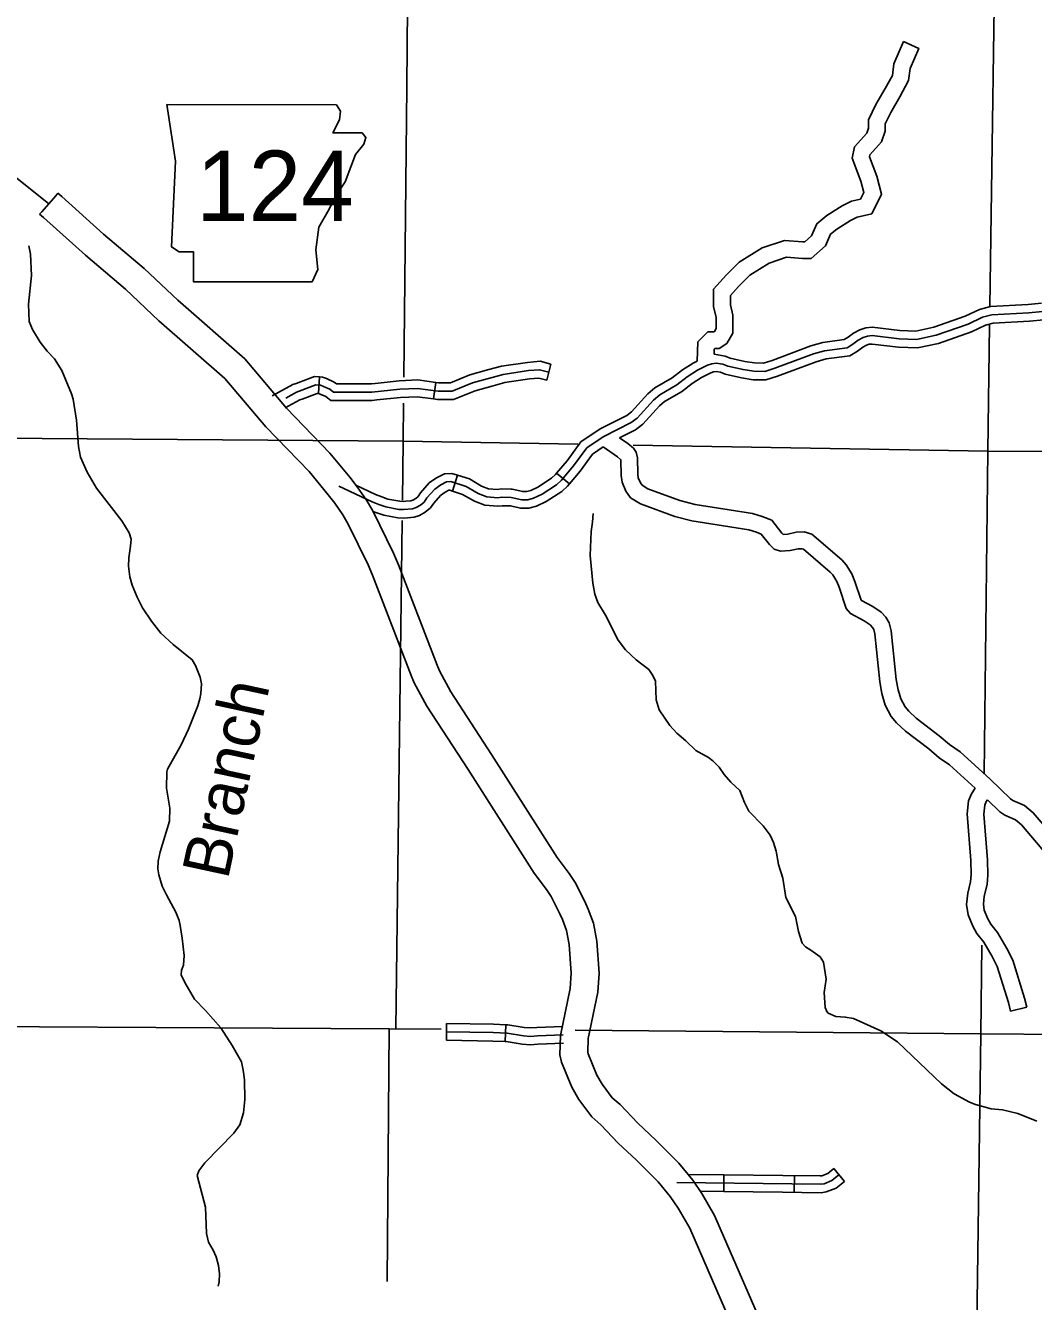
# Model space of a CAD drawing. Extents: x 1373862 to 1376999, y 1168398 to 1170455.
# Drawn here: x 1375806.5 to 1375987.3, y 1168745.9 to 1168974.9 of the extents above; entities that cross this region are included whole.
import ezdxf

# ---------------------------------------------------------------- set-up
doc = ezdxf.new("R2010")
doc.units = 0
for name, color, linetype in [('Level 10', 7, 'Continuous'), ('Level 21', 7, 'Continuous'), ('Level 32', 7, 'Continuous'), ('Level 35', 7, 'Continuous'), ('Level 4', 7, 'Continuous'), ('Level 45', 7, 'Continuous'), ('Level 46', 7, 'Continuous'), ('Level 5', 7, 'Continuous')]:
    doc.layers.add(name, color=color, linetype=linetype)

msp = doc.modelspace()

# ---------------------------------------------------------------- linework, layer by layer
at = {"layer": 'Level 10'}
for points in [[(1375810.66, 1168942.85), (1375802.81, 1168949.14), (1375798.84, 1168952.2), (1375796.61, 1168953.74), (1375794.39, 1168954.87), (1375775.91, 1168959.64), (1375772.5, 1168960.73), (1375771.74, 1168961.21), (1375770.37, 1168962.36), (1375769.5, 1168963.6), (1375769.9, 1169002.68)], [(1375907.42, 1168793.06), (1375909.18, 1168801.4), (1375909.38, 1168804.82), (1375908.98, 1168810.57), (1375908.37, 1168813.81), (1375907.44, 1168816.28), (1375906.83, 1168817.69), (1375905.11, 1168821.05), (1375904.04, 1168822.71), (1375901.86, 1168825.59), (1375890.1, 1168844.04), (1375882.79, 1168855.29), (1375880.73, 1168859.09), (1375880.3, 1168860.1), (1375873.38, 1168878.1), (1375872.5, 1168880.18), (1375868.76, 1168887.77), (1375867.63, 1168889.72), (1375865.99, 1168892.1), (1375864.65, 1168893.8), (1375861.07, 1168898.14), (1375853.31, 1168906.19), (1375845.81, 1168915.03), (1375833.76, 1168925.58), (1375827.75, 1168931.3), (1375820.47, 1168937.44), (1375812.95, 1168944.22), (1375812.27, 1168944.77)], [(1375808.96, 1168941.01), (1375809.71, 1168940.41), (1375817.19, 1168933.67), (1375824.41, 1168927.58), (1375830.39, 1168921.89), (1375842.24, 1168911.51), (1375849.6, 1168902.83), (1375857.34, 1168894.81), (1375860.76, 1168890.66), (1375861.96, 1168889.13), (1375863.4, 1168887.05), (1375864.34, 1168885.41), (1375867.95, 1168878.1), (1375868.74, 1168876.23), (1375875.66, 1168858.23), (1375876.22, 1168856.92), (1375878.49, 1168852.73), (1375885.89, 1168841.34), (1375897.75, 1168822.74), (1375899.94, 1168819.84), (1375900.77, 1168818.55), (1375902.3, 1168815.56), (1375902.8, 1168814.41), (1375903.54, 1168812.45), (1375904.01, 1168809.93), (1375904.37, 1168804.79), (1375904.21, 1168802.07), (1375902.43, 1168793.65)], [(1375902.43, 1168793.65), (1375902.35, 1168790.14), (1375902.63, 1168788.81), (1375904.5, 1168784.33), (1375905.74, 1168782.14), (1375908.07, 1168779.04), (1375909.69, 1168777.61), (1375912.79, 1168774.31), (1375916.12, 1168771.22), (1375919.99, 1168767.37), (1375922.16, 1168764.7), (1375923.56, 1168762.62), (1375925.64, 1168759.06), (1375935.97, 1168735.29)], [(1375940.58, 1168737.24), (1375930.11, 1168761.33), (1375927.8, 1168765.29), (1375926.18, 1168767.68), (1375923.71, 1168770.73), (1375919.59, 1168774.82), (1375916.32, 1168777.86), (1375913.17, 1168781.21), (1375911.76, 1168782.45), (1375909.93, 1168784.88), (1375909, 1168786.53), (1375907.42, 1168790.31), (1375907.36, 1168790.61), (1375907.42, 1168793.06)]]:
    msp.add_lwpolyline(points, dxfattribs=at)
msp.add_arc((1375767.96, 1168980.41), 56.86, 316.1417, 321.187, dxfattribs=at)
at = {"layer": 'Level 21'}
msp.add_lwpolyline([(1375831.83, 1168960.69), (1375833.35, 1168950.54), (1375832.68, 1168935.14), (1375834.03, 1168934.29), (1375836.57, 1168934.29), (1375836.57, 1168928.88), (1375857.88, 1168928.88), (1375858.9, 1168931.08), (1375858.56, 1168934.63), (1375859.07, 1168938.69), (1375860.93, 1168941.91), (1375862.11, 1168944.28), (1375863.81, 1168946.81), (1375864.82, 1168949.52), (1375865.67, 1168951.72), (1375867.19, 1168953.58), (1375867.53, 1168954.76), (1375866.85, 1168955.61), (1375861.61, 1168955.61), (1375862.79, 1168957.98), (1375862.96, 1168959.5), (1375862.26, 1168960.67)], close=True, dxfattribs=at)
at = {"layer": 'Level 32'}
for p, q in [((1375881.98, 1168792.77), (1375882.03, 1168795.77)), ((1375892.5, 1168792.54), (1375892.63, 1168795.54)), ((1375951.5, 1168769.73), (1375953.4, 1168767.41)), ((1375931.8, 1168768.62), (1375931.76, 1168765.62)), ((1375944.41, 1168765.46), (1375944.45, 1168768.46))]:
    msp.add_line(p, q, dxfattribs=at)
for points in [[(1375882.03, 1168795.77), (1375890.42, 1168795.63), (1375892.63, 1168795.54)], [(1375892.63, 1168795.54), (1375893.03, 1168795.52), (1375895.96, 1168795.05), (1375897.09, 1168794.97), (1375898.23, 1168795.05), (1375902.9, 1168795.23)], [(1375881.98, 1168792.77), (1375890.33, 1168792.63), (1375892.5, 1168792.54)], [(1375882.01, 1168794.27), (1375890.37, 1168794.13), (1375892.88, 1168794.03), (1375895.79, 1168793.56), (1375897.1, 1168793.46), (1375898.32, 1168793.56), (1375902.95, 1168793.74)], [(1375892.5, 1168792.54), (1375892.72, 1168792.53), (1375895.61, 1168792.06), (1375897.1, 1168791.96), (1375898.41, 1168792.06), (1375903.01, 1168792.24)], [(1375951.5, 1168769.73), (1375950.43, 1168768.86), (1375949.37, 1168768.46), (1375949.04, 1168768.41), (1375942.36, 1168768.49)], [(1375931.8, 1168768.62), (1375925.35, 1168768.7)], [(1375942.36, 1168768.49), (1375931.8, 1168768.62)], [(1375953.4, 1168767.41), (1375951.95, 1168766.23), (1375950.15, 1168765.55), (1375949.26, 1168765.4), (1375942.32, 1168765.49)], [(1375931.76, 1168765.62), (1375927.57, 1168765.68)], [(1375942.32, 1168765.49), (1375931.76, 1168765.62)]]:
    msp.add_lwpolyline(points, dxfattribs=at)
at = {"layer": 'Level 35'}
for points in [[(1375843.53, 1168791.82), (1375841.51, 1168794.98), (1375838.78, 1168798.09), (1375836.77, 1168800.12), (1375835.02, 1168803.13), (1375834.37, 1168804.53), (1375834.47, 1168805.33), (1375834.78, 1168806.23), (1375834.93, 1168807.96), (1375834.59, 1168811.06), (1375834.21, 1168813.36), (1375834, 1168814.26), (1375833.41, 1168815.74), (1375831.73, 1168818.85), (1375830.97, 1168820.45), (1375830.38, 1168822.43), (1375830.19, 1168823.51), (1375830.24, 1168824.89), (1375830.59, 1168826.56), (1375832.29, 1168832.08), (1375832.37, 1168834.43), (1375831.73, 1168837.99), (1375831.79, 1168840.96), (1375831.94, 1168841.44), (1375834.4, 1168845.77), (1375835.7, 1168848.62), (1375837.37, 1168852.76), (1375837.76, 1168854.07), (1375837.91, 1168855.01), (1375838.04, 1168856.75), (1375837.81, 1168857.95), (1375836.98, 1168860.01), (1375836.39, 1168861.05), (1375832.96, 1168863.81), (1375830.75, 1168865.8), (1375829.07, 1168867.99), (1375827.45, 1168870.38), (1375826.49, 1168872.3), (1375825.62, 1168874.47), (1375825.17, 1168875.93), (1375824.95, 1168877.85), (1375824.98, 1168879.36), (1375825.31, 1168881.44), (1375825.4, 1168882.67), (1375825.05, 1168883.83), (1375823.71, 1168885.98), (1375819.22, 1168891.86), (1375817.54, 1168894.71), (1375816.3, 1168897.39), (1375815.98, 1168899.31), (1375815.63, 1168904.07), (1375815.02, 1168907.84), (1375814.71, 1168908.8), (1375812.96, 1168912.99), (1375811.65, 1168915.04), (1375810.31, 1168916.42), (1375809.1, 1168918.05), (1375807.68, 1168920.32), (1375807.11, 1168921.76), (1375806.99, 1168924.85), (1375807.51, 1168930), (1375807.34, 1168933.83), (1375807.07, 1168935.33)], [(1375908.32, 1168887.31), (1375908.23, 1168885.77), (1375907.97, 1168884.05), (1375907.8, 1168879.74), (1375908.28, 1168874.8), (1375908.62, 1168872.8), (1375909.14, 1168871.31), (1375910.51, 1168869.06), (1375912.83, 1168864.56), (1375914.11, 1168862.84), (1375916.06, 1168861.02), (1375918.29, 1168859.32), (1375919.02, 1168858.23), (1375919.49, 1168857.23), (1375919.63, 1168853.89), (1375920.17, 1168852.04), (1375922.09, 1168849.28), (1375923.31, 1168847.85), (1375924.97, 1168846.51), (1375926.76, 1168844.77), (1375929, 1168843.53), (1375929.81, 1168842.92), (1375930.94, 1168841.79), (1375931.83, 1168840.44), (1375933.01, 1168839.07), (1375934.65, 1168837.61), (1375935.47, 1168835.46), (1375936.28, 1168833.87), (1375938.85, 1168831.25), (1375940.06, 1168829.58), (1375940.67, 1168828.27), (1375941.17, 1168826.68), (1375941.6, 1168824.32), (1375942.35, 1168821.85), (1375942.89, 1168818.37), (1375944.64, 1168815), (1375945.17, 1168812.31), (1375945.84, 1168810.22), (1375946.4, 1168809.54), (1375947.41, 1168808.95), (1375949.04, 1168807.72), (1375949.63, 1168806.76), (1375950.16, 1168803.76), (1375949.75, 1168801.31), (1375949.94, 1168798.67), (1375950.25, 1168797.93), (1375950.51, 1168797.6), (1375951.88, 1168797.06), (1375953.56, 1168796.94), (1375955.04, 1168796.65), (1375959.94, 1168794.44), (1375962.93, 1168792.46), (1375970.85, 1168784.94), (1375973.13, 1168783.13), (1375975.88, 1168781.66), (1375976.91, 1168781.21), (1375979.73, 1168780.44), (1375981.76, 1168780.29), (1375984.55, 1168779.62), (1375987.94, 1168778.24)], [(1375843.53, 1168791.82), (1375845.22, 1168788.91), (1375845.52, 1168787.38), (1375845.73, 1168785.64), (1375845.83, 1168782.13), (1375845.55, 1168779.74), (1375844.89, 1168777.59), (1375843.85, 1168776.1), (1375838.66, 1168770.76), (1375837.55, 1168769.36), (1375837.28, 1168768.51), (1375838.75, 1168762.8), (1375838.91, 1168758.07), (1375839.28, 1168756.54), (1375840.1, 1168755.11), (1375840.66, 1168753.92), (1375841.08, 1168752.33), (1375841.25, 1168750.83), (1375841.19, 1168749.43), (1375841.03, 1168748.65)]]:
    msp.add_lwpolyline(points, dxfattribs=at)
at = {"layer": 'Level 4'}
for points in [[(1375881.05, 1168794.75), (1375871.72, 1168794.83), (1375767.06, 1168795.43)], [(1375977.91, 1168793.92), (1375905.11, 1168794.55)], [(1375977.91, 1168793.92), (1376008.61, 1168793.71)]]:
    msp.add_lwpolyline(points, dxfattribs=at)
at = {"layer": 'Level 45'}
for p, q in [((1375900.75, 1168914.12), (1375899.99, 1168911.22)), ((1375859.22, 1168911.82), (1375859.01, 1168908.83)), ((1375880.07, 1168910.83), (1375879.66, 1168907.86)), ((1375884, 1168894.18), (1375883.09, 1168891.32)), ((1375901.77, 1168894.54), (1375904.07, 1168892.61))]:
    msp.add_line(p, q, dxfattribs=at)
for points in [[(1375988.98, 1168923.56), (1375986.52, 1168923.34), (1375979.89, 1168922.97), (1375978.19, 1168922.51), (1375975.62, 1168921.31), (1375969.88, 1168919.28), (1375966.37, 1168918.53), (1375963.22, 1168918.63), (1375958.39, 1168919.23), (1375957.55, 1168919.15), (1375956.75, 1168918.9), (1375955.89, 1168918.41), (1375954.93, 1168917.68), (1375953.9, 1168917.06), (1375949.84, 1168916.52), (1375947.88, 1168915.95), (1375940.93, 1168913.37), (1375939.11, 1168912.81), (1375937.16, 1168912.82), (1375935.24, 1168913.13), (1375932.47, 1168913.75), (1375931.61, 1168914.1), (1375930.4, 1168914.29), (1375929.6, 1168914.18), (1375928.84, 1168913.94), (1375927.03, 1168913), (1375925.21, 1168911.85), (1375923.34, 1168910.37), (1375920.27, 1168908.62), (1375919.17, 1168907.67), (1375916.19, 1168904.42), (1375915.14, 1168903.61), (1375910.11, 1168901.07), (1375907.16, 1168899.08)], [(1375900.75, 1168914.12), (1375898.83, 1168914.63), (1375896.52, 1168914.43), (1375891.87, 1168913.74), (1375889.61, 1168913.12)], [(1375859.22, 1168911.82), (1375858.32, 1168911.89), (1375855.05, 1168910.65), (1375854.45, 1168910.44), (1375850.72, 1168908.42)], [(1375900.37, 1168912.67), (1375898.7, 1168913.11), (1375896.7, 1168912.94), (1375892.18, 1168912.27), (1375886.66, 1168910.77), (1375882.99, 1168909.26), (1375880.48, 1168909.26), (1375876.8, 1168909.76), (1375873.62, 1168909.6), (1375868.61, 1168909.09), (1375864.43, 1168909.09), (1375861.75, 1168909.09), (1375861.08, 1168909.6), (1375859.9, 1168910.12), (1375859.39, 1168910.31), (1375858.55, 1168910.37), (1375855.56, 1168909.24), (1375855.06, 1168909.06), (1375853.16, 1168908.03)], [(1375869.21, 1168910.66), (1375868.53, 1168910.59), (1375864.43, 1168910.59), (1375862.25, 1168910.59), (1375861.85, 1168910.9), (1375860.47, 1168911.5), (1375859.72, 1168911.79), (1375859.22, 1168911.82)], [(1375889.61, 1168913.12), (1375886.18, 1168912.19), (1375882.69, 1168910.76), (1375880.58, 1168910.76), (1375880.07, 1168910.83)], [(1375899.99, 1168911.22), (1375898.57, 1168911.59), (1375896.87, 1168911.45), (1375892.49, 1168910.8), (1375890.4, 1168910.23)], [(1375880.07, 1168910.83), (1375876.86, 1168911.27), (1375873.51, 1168911.09), (1375869.21, 1168910.66)], [(1375890.4, 1168910.23), (1375887.15, 1168909.34), (1375883.28, 1168907.76), (1375880.38, 1168907.76), (1375879.66, 1168907.86)], [(1375859.01, 1168908.83), (1375858.77, 1168908.85), (1375856.08, 1168907.83), (1375855.67, 1168907.69), (1375853.02, 1168906.25)], [(1375869.51, 1168907.68), (1375868.68, 1168907.59), (1375864.43, 1168907.59), (1375861.25, 1168907.59), (1375860.32, 1168908.29), (1375859.33, 1168908.73), (1375859.06, 1168908.83), (1375859.01, 1168908.83)], [(1375879.66, 1168907.86), (1375876.74, 1168908.26), (1375873.74, 1168908.1), (1375869.51, 1168907.68)], [(1375909.55, 1168902.47), (1375906.12, 1168900.16), (1375903.64, 1168896.77), (1375901.77, 1168894.54)], [(1375907.16, 1168899.08), (1375904.8, 1168895.86), (1375902.63, 1168893.28), (1375901.74, 1168892.47), (1375899.15, 1168890.77), (1375897.63, 1168890.03), (1375896.59, 1168889.77), (1375895.51, 1168889.78), (1375893.6, 1168890.2), (1375891.9, 1168890.23), (1375891.2, 1168890.14), (1375889.22, 1168890.29), (1375887.67, 1168890.88), (1375885.52, 1168892.14), (1375882.77, 1168893.03), (1375882.03, 1168892.98), (1375880.97, 1168892.45), (1375879.89, 1168891.68), (1375878.5, 1168890.09), (1375877.99, 1168889.36), (1375877.31, 1168888.8), (1375876.55, 1168888.37), (1375875.89, 1168888.14), (1375874.29, 1168887.99), (1375873.45, 1168888.02), (1375871.12, 1168888.47), (1375869.88, 1168888.9), (1375868.69, 1168889.37), (1375862.7, 1168892.23)], [(1375910.14, 1168899.25), (1375908.23, 1168897.97), (1375906, 1168894.92), (1375904.07, 1168892.61)], [(1375884, 1168894.18), (1375882.95, 1168894.51), (1375881.64, 1168894.43), (1375880.21, 1168893.72), (1375878.9, 1168892.78), (1375877.34, 1168891), (1375876.9, 1168890.37), (1375876.47, 1168890.01), (1375875.95, 1168889.72), (1375875.58, 1168889.59), (1375874.73, 1168889.51)], [(1375893.58, 1168891.68), (1375891.82, 1168891.7), (1375891.16, 1168891.62), (1375889.54, 1168891.74), (1375888.31, 1168892.21), (1375886.12, 1168893.5), (1375884, 1168894.18)], [(1375901.77, 1168894.54), (1375901.57, 1168894.3), (1375900.84, 1168893.64), (1375898.42, 1168892.05), (1375897.12, 1168891.42), (1375896.41, 1168891.24), (1375895.68, 1168891.25), (1375893.78, 1168891.67), (1375893.58, 1168891.68)], [(1375874.73, 1168889.51), (1375874.25, 1168889.47), (1375873.62, 1168889.49), (1375871.5, 1168889.89), (1375870.39, 1168890.28), (1375869.28, 1168890.72), (1375865.75, 1168892.41)], [(1375883.09, 1168891.32), (1375882.57, 1168891.48), (1375882.43, 1168891.47), (1375881.76, 1168891.14), (1375880.93, 1168890.54), (1375879.7, 1168889.14), (1375879.12, 1168888.32), (1375878.18, 1168887.53), (1375877.18, 1168886.97), (1375876.22, 1168886.64), (1375875.01, 1168886.53)], [(1375893.53, 1168888.68), (1375891.98, 1168888.7), (1375891.24, 1168888.61), (1375888.88, 1168888.78), (1375887.01, 1168889.5), (1375884.89, 1168890.74), (1375883.09, 1168891.32)], [(1375904.07, 1168892.61), (1375903.74, 1168892.22), (1375902.68, 1168891.26), (1375899.9, 1168889.43), (1375898.16, 1168888.59), (1375896.78, 1168888.24), (1375895.33, 1168888.25), (1375893.42, 1168888.68)], [(1375875.01, 1168886.53), (1375874.33, 1168886.46), (1375873.27, 1168886.5), (1375870.73, 1168886.99), (1375868.81, 1168887.65)], [(1375952.43, 1168768.59), (1375951.18, 1168767.57), (1375949.75, 1168767.03), (1375949.14, 1168766.93), (1375923.34, 1168767.26)]]:
    msp.add_lwpolyline(points, dxfattribs=at)
at = {"layer": 'Level 46'}
for points in [[(1375926.98, 1168914.66), (1375927.11, 1168918.11), (1375928.92, 1168919.92), (1375930.03, 1168919.92), (1375930.09, 1168919.95), (1375930.41, 1168920.49), (1375930.41, 1168922.51), (1375929.94, 1168924.41), (1375929.94, 1168927.54), (1375932.24, 1168930.13), (1375934.53, 1168932.42), (1375938.62, 1168934.98), (1375942.64, 1168936.32), (1375945.97, 1168936.07), (1375946.3, 1168936.07), (1375947.53, 1168937.14), (1375948.48, 1168939.3), (1375950.25, 1168940.77), (1375953.01, 1168942.52), (1375954.67, 1168943.35), (1375956.29, 1168943.71), (1375956.9, 1168944.94), (1375956.35, 1168946.93), (1375954.8, 1168951.07), (1375955.21, 1168953.08), (1375957.41, 1168955.53), (1375957.71, 1168956.43), (1375957.71, 1168957.96), (1375959.07, 1168960.7), (1375960.75, 1168963.57), (1375962.02, 1168965.9), (1375962.25, 1168967.98), (1375964, 1168971.98)], [(1375930.03, 1168915.87), (1375930.06, 1168916.82), (1375930.16, 1168916.92), (1375930.94, 1168916.92), (1375932.31, 1168917.83), (1375933.41, 1168919.66), (1375933.41, 1168922.88), (1375932.94, 1168924.78), (1375932.94, 1168926.4), (1375934.43, 1168928.07), (1375936.41, 1168930.06), (1375939.91, 1168932.25), (1375943.02, 1168933.29), (1375945.86, 1168933.07), (1375947.43, 1168933.07), (1375950, 1168935.32), (1375950.94, 1168937.44), (1375952.02, 1168938.34), (1375954.49, 1168939.91), (1375955.68, 1168940.51), (1375958.33, 1168941.1), (1375960.09, 1168944.62), (1375959.21, 1168947.86), (1375957.91, 1168951.32), (1375957.99, 1168951.68), (1375960.06, 1168953.99), (1375960.71, 1168955.94), (1375960.71, 1168957.25), (1375961.71, 1168959.27), (1375963.36, 1168962.1), (1375964.94, 1168964.99), (1375965.18, 1168967.19), (1375966.75, 1168970.78), (1375964, 1168971.98)], [(1375930.03, 1168915.87), (1375932.01, 1168915.55), (1375932.92, 1168915.18), (1375935.52, 1168914.6), (1375937.28, 1168914.32), (1375938.88, 1168914.31), (1375940.45, 1168914.79), (1375947.4, 1168917.37), (1375949.52, 1168918), (1375953.39, 1168918.5), (1375954.09, 1168918.93), (1375955.06, 1168919.67), (1375956.15, 1168920.29), (1375957.25, 1168920.62), (1375958.4, 1168920.74), (1375963.34, 1168920.13), (1375966.23, 1168920.04), (1375969.48, 1168920.73), (1375975.05, 1168922.7), (1375977.68, 1168923.93), (1375979.65, 1168924.45), (1375986.41, 1168924.83), (1375988.79, 1168925.04)], [(1375913.06, 1168900.88), (1375915.94, 1168902.34), (1375917.21, 1168903.31), (1375920.22, 1168906.6), (1375921.14, 1168907.39), (1375924.18, 1168909.12), (1375926.08, 1168910.62), (1375927.78, 1168911.7), (1375929.42, 1168912.55), (1375929.94, 1168912.72), (1375930.38, 1168912.77), (1375931.2, 1168912.65), (1375932.02, 1168912.31), (1375934.96, 1168911.65), (1375937.04, 1168911.32), (1375939.33, 1168911.31), (1375941.41, 1168911.95), (1375948.35, 1168914.52), (1375950.15, 1168915.05), (1375954.41, 1168915.61), (1375955.78, 1168916.44), (1375956.72, 1168917.16), (1375957.35, 1168917.52), (1375957.85, 1168917.67), (1375958.37, 1168917.72), (1375963.1, 1168917.13), (1375966.5, 1168917.03), (1375970.29, 1168917.84), (1375976.19, 1168919.92), (1375978.71, 1168921.1), (1375980.13, 1168921.48), (1375986.63, 1168921.84), (1375989.17, 1168922.07)], [(1375909.55, 1168902.47), (1375914.34, 1168904.89), (1375915.18, 1168905.53), (1375918.13, 1168908.75), (1375919.4, 1168909.85), (1375922.5, 1168911.62), (1375924.34, 1168913.07), (1375926.28, 1168914.3), (1375926.98, 1168914.66)], [(1375913.06, 1168900.88), (1375914.55, 1168899.86), (1375915.54, 1168899.01), (1375916.04, 1168898.29), (1375916.26, 1168897.3), (1375916.32, 1168894.37), (1375916.42, 1168893.72), (1375916.82, 1168892.78), (1375917.13, 1168892.36), (1375918.12, 1168891.74), (1375923.86, 1168889.64), (1375926.65, 1168888.94), (1375936.94, 1168887.31), (1375938.63, 1168886.79), (1375940.36, 1168886.08), (1375942.2, 1168883.76), (1375942.4, 1168883.56), (1375943.25, 1168883.62), (1375944.74, 1168883.93), (1375946.19, 1168884), (1375947.54, 1168883.57), (1375952.96, 1168878.97), (1375953.75, 1168878.11), (1375954.74, 1168876.45), (1375955.29, 1168875.12), (1375956.43, 1168871.73), (1375956.45, 1168871.69), (1375958.48, 1168870.6), (1375959.98, 1168869.59), (1375960.83, 1168868.67), (1375961.46, 1168867.69), (1375961.82, 1168866.22), (1375962.72, 1168857.51), (1375963.05, 1168855.68), (1375963.54, 1168854.04), (1375964.29, 1168852.58), (1375964.95, 1168851.8), (1375966.29, 1168850.56), (1375970.43, 1168847.41), (1375972.26, 1168845.86), (1375974.16, 1168844.51), (1375979.56, 1168839.61), (1375983.19, 1168836.09), (1375983.63, 1168835.8), (1375985.71, 1168834.88), (1375987.29, 1168833.59), (1375990.85, 1168829.37)], [(1375910.14, 1168899.25), (1375912.71, 1168897.48), (1375913.25, 1168897.02), (1375913.27, 1168896.94), (1375913.33, 1168894.1), (1375913.52, 1168892.9), (1375914.19, 1168891.29), (1375915.05, 1168890.12), (1375916.8, 1168889.03), (1375922.98, 1168886.77), (1375926.05, 1168886), (1375936.26, 1168884.38), (1375937.62, 1168883.96), (1375938.5, 1168883.6), (1375939.97, 1168881.75), (1375940.82, 1168880.9), (1375941.96, 1168880.52), (1375943.66, 1168880.64), (1375945.12, 1168880.95), (1375945.8, 1168880.98), (1375946.06, 1168880.9), (1375950.88, 1168876.8), (1375951.33, 1168876.31), (1375952.05, 1168875.1), (1375952.48, 1168874.07), (1375953.75, 1168870.27), (1375954.49, 1168869.34), (1375956.93, 1168868.03), (1375958.01, 1168867.3), (1375958.45, 1168866.82), (1375958.67, 1168866.49), (1375958.85, 1168865.71), (1375959.75, 1168857.09), (1375960.13, 1168854.99), (1375960.75, 1168852.91), (1375961.79, 1168850.9), (1375962.78, 1168849.73), (1375964.35, 1168848.26), (1375968.55, 1168845.07), (1375970.42, 1168843.48), (1375972.27, 1168842.17), (1375976.86, 1168838.01)], [(1375976.86, 1168838.01), (1375976.21, 1168837.02), (1375975.65, 1168835.74), (1375975.43, 1168833.38), (1375976.09, 1168825), (1375976.17, 1168822.5), (1375976.06, 1168821.22), (1375975.56, 1168819.19), (1375975.31, 1168817.15), (1375975.6, 1168815.29), (1375976.43, 1168813.27), (1375977.15, 1168811.91), (1375978.42, 1168810.36), (1375979.94, 1168807.8), (1375980.84, 1168806.02), (1375982.86, 1168799.53), (1375983.22, 1168798), (1375986.14, 1168798.69)], [(1375979.07, 1168835.91), (1375978.86, 1168835.59), (1375978.59, 1168834.98), (1375978.44, 1168833.36), (1375979.09, 1168825.16), (1375979.17, 1168822.41), (1375979.03, 1168820.73), (1375978.51, 1168818.65), (1375978.34, 1168817.21), (1375978.51, 1168816.1), (1375979.15, 1168814.53), (1375979.66, 1168813.58), (1375980.89, 1168812.09), (1375982.57, 1168809.24), (1375983.63, 1168807.14), (1375985.75, 1168800.32), (1375986.14, 1168798.69)], [(1375979.07, 1168835.91), (1375981.31, 1168833.74), (1375982.19, 1168833.16), (1375984.13, 1168832.3), (1375985.17, 1168831.45), (1375988.53, 1168827.47), (1375992.66, 1168822.29), (1375994.65, 1168820.84), (1375997.34, 1168819.55), (1376001.76, 1168818.16), (1376004.15, 1168817.26)]]:
    msp.add_lwpolyline(points, dxfattribs=at)
at = {"layer": 'Level 5'}
for points in [[(1375979.52, 1168924.46), (1375980.66, 1169003.12), (1375980.72, 1169012.19)], [(1375875.21, 1168999.88), (1375874.86, 1168963.85)], [(1375874.86, 1168963.85), (1375874.35, 1168911.76)], [(1375978.46, 1168840.59), (1375979.15, 1168898.49), (1375979.47, 1168921.08)], [(1375874.31, 1168907.12), (1375874.24, 1168900.29), (1375874.11, 1168889.71)], [(1375749.07, 1168900.91), (1375768.86, 1168901.09), (1375874.24, 1168900.29), (1375905.56, 1168899.76)], [(1375915.48, 1168899.59), (1375979.15, 1168898.49), (1376037.51, 1168898.19)], [(1375874.07, 1168886.07), (1375872.93, 1168794.83)], [(1375976.48, 1168689.17), (1375977.91, 1168793.92), (1375978.1, 1168809.85)], [(1375871.72, 1168794.83), (1375871.37, 1168749.47)]]:
    msp.add_lwpolyline(points, dxfattribs=at)

# ---------------------------------------------------------------- texts
at = {"layer": 'Level 21'}
msp.add_text('124', height=12.66, dxfattribs=at).set_placement((1375837.09, 1168939.77))
at = {"layer": 'Level 35'}
msp.add_text('Branch', height=8.44, rotation=77.8047, dxfattribs=at).set_placement((1375842.75, 1168821.42))

doc.saveas('drawing.dxf')
